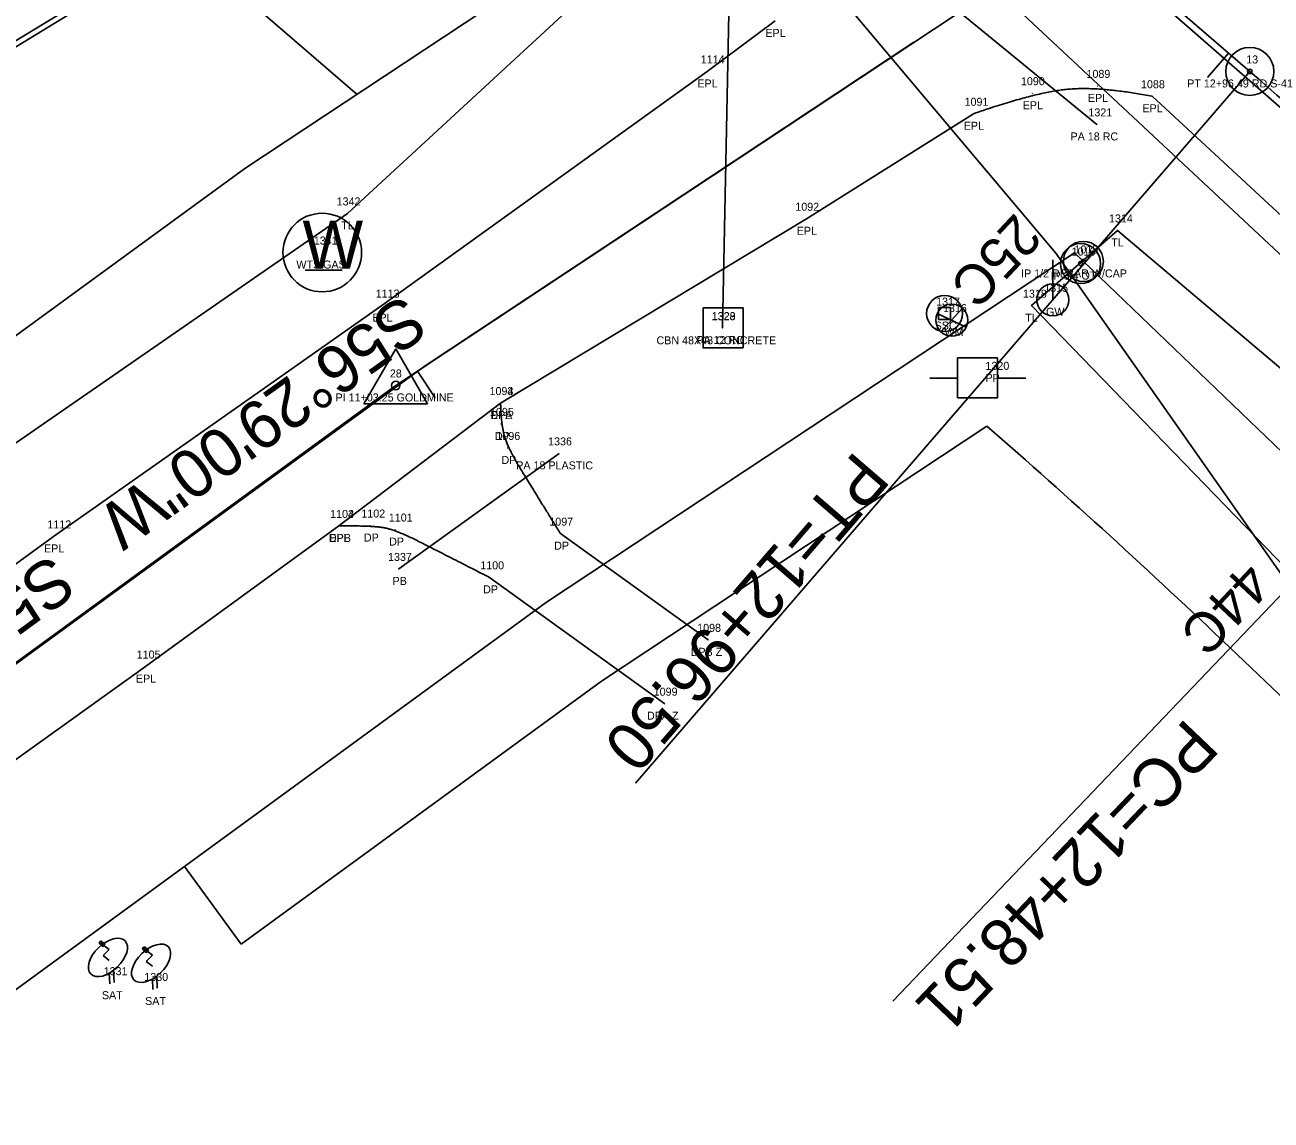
# Model space of a CAD drawing. Extents: x 1812113 to 1819860, y 1177395 to 1181185.
# Drawn here: x 1813697.5 to 1813853.2, y 1178492.8 to 1178629.6 of the extents above; entities that cross this region are included whole.
import ezdxf

# ---------------------------------------------------------------- set-up
doc = ezdxf.new("R2010")
doc.units = 0
for name, color, linetype in [('RD_EX_BldgApp', 7, 'Continuous'), ('RD_EX_BldgApp_txCode', 7, 'Continuous'), ('RD_EX_DR_Inlet', 7, 'Continuous'), ('RD_EX_DR_Inlet_txCode', 7, 'Continuous'), ('RD_EX_DR_Pipe', 7, 'Continuous'), ('RD_EX_DR_Pipe_txCode', 7, 'Continuous'), ('RD_EX_Driveway', 7, 'Continuous'), ('RD_EX_Driveway_txCode', 7, 'Continuous'), ('RD_EX_DV_Prop', 7, 'Continuous'), ('RD_EX_DV_Prop_txCode', 7, 'Continuous'), ('RD_EX_DV_PropPin', 7, 'Continuous'), ('RD_EX_Fence_Other', 7, 'Continuous'), ('RD_EX_Road', 7, 'Continuous'), ('RD_EX_Road_txCode', 7, 'Continuous'), ('RD_EX_RW', 7, 'Continuous'), ('RD_EX_UT', 7, 'Continuous'), ('RD_EX_UT_txCode', 7, 'Continuous'), ('RD_EX_VEG', 7, 'Continuous'), ('RD_EX_VEG_txCode', 7, 'Continuous'), ('RD_HC_CL', 7, 'Continuous'), ('RD_HC_Data', 7, 'Continuous'), ('RD_HC_Data_Tic', 7, 'Continuous'), ('RD_HC_txCode', 7, 'Continuous'), ('RD_PD_ALT3_LnLine', 7, 'Continuous'), ('RD_PD_PatLn1', 7, 'Continuous'), ('RD_PD_RW', 7, 'Continuous'), ('RD_SMD_Locator', 7, 'Continuous')]:
    doc.layers.add(name, color=color, linetype=linetype)

msp = doc.modelspace()

# ---------------------------------------------------------------- linework, layer by layer
at = {"layer": 'RD_EX_BldgApp'}
for p, q in [((1813707.25, 1178514.39), (1813706.86, 1178514.78)), ((1813708.04, 1178514.07), (1813706.93, 1178514.91)), ((1813707.1, 1178515.07), (1813707.53, 1178514.71)), ((1813707.14, 1178514.81), (1813707.14, 1178514.81)), ((1813707.25, 1178514.79), (1813707.25, 1178514.79)), ((1813707.53, 1178514.71), (1813707.25, 1178514.39)), ((1813707.27, 1178513.31), (1813708.04, 1178514.07)), ((1813712.65, 1178513.67), (1813712.26, 1178514.05)), ((1813713.44, 1178513.35), (1813712.33, 1178514.18)), ((1813712.5, 1178514.35), (1813712.93, 1178513.98)), ((1813712.54, 1178514.09), (1813712.54, 1178514.09)), ((1813712.65, 1178514.07), (1813712.65, 1178514.07)), ((1813712.93, 1178513.98), (1813712.65, 1178513.67)), ((1813708.04, 1178512.69), (1813707.27, 1178513.31)), ((1813712.67, 1178512.58), (1813713.44, 1178513.35)), ((1813713.44, 1178511.97), (1813712.67, 1178512.58)), ((1813708.04, 1178511.13), (1813708.11, 1178509.79)), ((1813708.58, 1178511.42), (1813708.65, 1178509.96)), ((1813713.98, 1178510.69), (1813714.05, 1178509.24)), ((1813713.44, 1178510.41), (1813713.51, 1178509.06))]:
    msp.add_line(p, q, dxfattribs=at)
for centre in [(1813707.88, 1178513.08), (1813713.28, 1178512.35)]:
    msp.add_ellipse(centre, major_axis=(-2.15, -2.07), ratio=0.564687, dxfattribs=at)
for centre in [(1813706.99, 1178514.92), (1813712.39, 1178514.2)]:
    msp.add_ellipse(centre, major_axis=(0.099, 0.164), ratio=0.846225, start_param=6.138676, end_param=9.218032, dxfattribs=at)
at = {"layer": 'RD_EX_DR_Inlet'}
msp.add_line((1813787.23, 1178589.25), (1813787.23, 1178594.25), dxfattribs=at)
msp.add_lwpolyline([(1813787.23, 1178589.25), (1813787.23, 1178594.25), (1813782.23, 1178594.25), (1813782.23, 1178589.25)], close=True, dxfattribs=at)
at = {"layer": 'RD_EX_DR_Pipe'}
for p, q in [((1813831.42, 1178617.18), (1813794.72, 1178647.24)), ((1813784.67, 1178591.74), (1813785.57, 1178637.96)), ((1813764.24, 1178576.07), (1813744.22, 1178561.63))]:
    msp.add_line(p, q, dxfattribs=at)
at = {"layer": 'RD_EX_Driveway'}
for p, q in [((1813764.4, 1178566.04), (1813782.88, 1178552.77)), ((1813777.44, 1178544.79), (1813755.53, 1178560.58))]:
    msp.add_line(p, q, dxfattribs=at)
for points in [[(1813756.93, 1178582.36), (1813756.99, 1178579.76), (1813757.82, 1178576.75), (1813761.11, 1178571.4), (1813764.4, 1178566.04)], [(1813736.74, 1178567), (1813740.64, 1178567.05), (1813743.79, 1178566.55), (1813749.66, 1178563.57), (1813755.53, 1178560.58)]]:
    msp.add_open_spline(points, degree=2, dxfattribs=at)
at = {"layer": 'RD_EX_DV_Prop'}
for p, q in [((1813747.53, 1178587.02), (1813808.57, 1178627.44)), ((1814007.16, 1178429.49), (1813828.61, 1178601.13)), ((1813582.74, 1178466.98), (1813747.53, 1178587.02))]:
    msp.add_line(p, q, dxfattribs=at)
at = {"layer": 'RD_EX_DV_PropPin'}
for centre, radius in [((1813829.73, 1178600.06), 2.5), ((1813829.38, 1178599.79), 2.5), ((1813829.38, 1178599.79), 0.25), ((1813829.73, 1178600.06), 0.25)]:
    msp.add_circle(centre, radius, dxfattribs=at)
at = {"layer": 'RD_EX_Fence_Other'}
msp.add_lwpolyline([(1813689.16, 1178653.47), (1813706.15, 1178633.63), (1813541.42, 1178533.61)], dxfattribs=at)
at = {"layer": 'RD_EX_Road'}
for p, q in [((1813782.72, 1178623.8), (1813791.22, 1178630.12)), ((1813742.11, 1178594.54), (1813782.72, 1178623.8)), ((1813875.67, 1178586.1), (1813838.32, 1178620.7)), ((1813815.99, 1178618.51), (1813795.14, 1178605.39)), ((1813795.14, 1178605.39), (1813756.93, 1178582.36)), ((1813701.1, 1178565.69), (1813742.11, 1178594.54)), ((1813756.93, 1178582.36), (1813736.74, 1178567)), ((1813736.74, 1178567), (1813712.58, 1178549.43)), ((1813659.38, 1178535.26), (1813701.1, 1178565.69)), ((1813712.58, 1178549.43), (1813670.71, 1178519.43))]:
    msp.add_line(p, q, dxfattribs=at)
msp.add_open_spline([(1813838.32, 1178620.7), (1813831.51, 1178622), (1813823.35, 1178621.08), (1813815.99, 1178618.51)], degree=2, dxfattribs=at)
at = {"layer": 'RD_EX_RW'}
for p, q in [((1813782.5, 1178649.75), (1813724.98, 1178611.66)), ((1813724.98, 1178611.66), (1813565.45, 1178495.22)), ((1813828.61, 1178601.13), (1813762.68, 1178557.46)), ((1813762.68, 1178557.46), (1813604.36, 1178441.91))]:
    msp.add_line(p, q, dxfattribs=at)
at = {"layer": 'RD_EX_UT'}
for p, q in [((1813825.91, 1178595.26), (1813825.91, 1178600.26)), ((1813732.53, 1178598.96), (1813737.16, 1178598.96)), ((1813811.45, 1178593.56), (1813815.09, 1178591.85)), ((1813813.15, 1178594.29), (1813811.65, 1178594.29)), ((1813811.65, 1178594.29), (1813811.65, 1178592.79)), ((1813811.94, 1178591.27), (1813814.6, 1178594.16)), ((1813813.15, 1178592.79), (1813813.15, 1178594.29)), ((1813811.65, 1178592.79), (1813813.15, 1178592.79)), ((1813818.99, 1178588.01), (1813813.99, 1178588.01)), ((1813813.99, 1178588.01), (1813813.99, 1178583.01)), ((1813818.99, 1178583.01), (1813818.99, 1178588.01)), ((1813810.56, 1178585.45), (1813814.03, 1178585.45)), ((1813818.92, 1178585.45), (1813822.56, 1178585.45)), ((1813813.99, 1178583.01), (1813818.99, 1178583.01))]:
    msp.add_line(p, q, dxfattribs=at)
msp.add_lwpolyline([(1814122.48, 1178351.31), (1814099.73, 1178371.68), (1813807.05, 1178645.14), (1813817.45, 1178777.9), (1813883.81, 1178790.87)], dxfattribs=at)
for centre, radius in [((1813734.66, 1178601.17), 4.91), ((1813825.91, 1178595.26), 2), ((1813812.4, 1178593.54), 2.25), ((1813813.29, 1178592.73), 2)]:
    msp.add_circle(centre, radius, dxfattribs=at)
at = {"layer": 'RD_EX_VEG'}
for points in [[(1813569.58, 1178500.76), (1813635.35, 1178535.15), (1813737.8, 1178606.06), (1813775.9, 1178641.25), (1813752.75, 1178672.45), (1813690.46, 1178652.62), (1813708.11, 1178634.09), (1813540.71, 1178531.72)], [(1813964.65, 1178448.48), (1813984.61, 1178463.55), (1813943.71, 1178503.46), (1813904.65, 1178537.57), (1813863.79, 1178578.71), (1813833.99, 1178603.93), (1813823.24, 1178594.53), (1813964.65, 1178448.48)]]:
    msp.add_lwpolyline(points, dxfattribs=at)
at = {"layer": 'RD_HC_CL'}
for p, q in [((1813850.52, 1178623.8), (1813755.38, 1178705.86)), ((1813829.91, 1178641.57), (1813743.83, 1178584.56)), ((1813743.83, 1178584.56), (1813584.91, 1178468.56))]:
    msp.add_line(p, q, dxfattribs=at)
msp.add_arc((1813226.77, 1177900.71), 954.94, 46.33932, 49.21843, dxfattribs=at)
at = {"layer": 'RD_HC_Data'}
for p, q in [((1813850.52, 1178623.8), (1813773.78, 1178534.84)), ((1813886.05, 1178591.55), (1813805.93, 1178507.6)), ((1813739.86, 1178582.27), (1813743.83, 1178589.15)), ((1813743.83, 1178589.15), (1813747.8, 1178582.27)), ((1813739.86, 1178582.27), (1813747.8, 1178582.27))]:
    msp.add_line(p, q, dxfattribs=at)
for centre, radius in [((1813850.52, 1178623.8), 3), ((1813850.52, 1178623.8), 0.282), ((1813743.83, 1178584.56), 0.529)]:
    msp.add_circle(centre, radius, dxfattribs=at)
at = {"layer": 'RD_HC_Data_Tic'}
for p, q in [((1813847.86, 1178626.09), (1813845.25, 1178623.06)), ((1813746.54, 1178586.35), (1813748.75, 1178583.02))]:
    msp.add_line(p, q, dxfattribs=at)
at = {"layer": 'RD_PD_ALT3_LnLine'}
for p, q in [((1813826.31, 1178601.1), (1813793.67, 1178639.81)), ((1813854.64, 1178560.7), (1813826.31, 1178601.1))]:
    msp.add_line(p, q, dxfattribs=at)
at = {"layer": 'RD_PD_PatLn1'}
msp.add_line((1813775.64, 1178688.14), (1813886.05, 1178591.55), dxfattribs=at)
at = {"layer": 'RD_PD_RW'}
for p, q in [((1813739, 1178620.94), (1813706.39, 1178649.07)), ((1813817.66, 1178579.49), (1813769.53, 1178547.61)), ((1813883.18, 1178518.26), (1813848.08, 1178551.76)), ((1813769.53, 1178547.61), (1813724.52, 1178514.75)), ((1813724.52, 1178514.75), (1813717.44, 1178524.45))]:
    msp.add_line(p, q, dxfattribs=at)
msp.add_arc((1813226.77, 1177900.71), 899.94, 46.33932, 48.95957, dxfattribs=at)
at = {"layer": 'RD_SMD_Locator'}
for centre in [(1813782.72, 1178623.8), (1813850.52, 1178623.8), (1813823.35, 1178621.08), (1813831.51, 1178622), (1813838.32, 1178620.7), (1813815.99, 1178618.51), (1813831.42, 1178617.18), (1813737.8, 1178606.06), (1813795.14, 1178605.39), (1813833.99, 1178603.93), (1813742.11, 1178594.54), (1813823.24, 1178594.53), (1813784.67, 1178591.74), (1813743.83, 1178584.56), (1813756.93, 1178582.36), (1813756.93, 1178582.36), (1813756.99, 1178579.76), (1813757.82, 1178576.75), (1813764.24, 1178576.07), (1813736.74, 1178567), (1813736.74, 1178567), (1813740.64, 1178567.05), (1813743.79, 1178566.55), (1813701.1, 1178565.69), (1813764.4, 1178566.04), (1813744.22, 1178561.63), (1813755.53, 1178560.58), (1813782.88, 1178552.77), (1813712.58, 1178549.43), (1813777.44, 1178544.79)]:
    msp.add_circle(centre, 0.001, dxfattribs=at)

# ---------------------------------------------------------------- texts
at = {"layer": 'RD_EX_BldgApp_txCode'}
for s, p in [('1331', (1813707.35, 1178510.86)), ('1330', (1813712.43, 1178510.14)), ('SAT', (1813707.13, 1178507.86)), ('SAT', (1813712.53, 1178507.14))]:
    msp.add_text(s, height=1, dxfattribs=at).set_placement(p)
at = {"layer": 'RD_EX_DR_Inlet_txCode'}
for s, p in [('1328', (1813783.3, 1178592.7)), ('CBN 48X48 CONCRETE', (1813776.41, 1178589.7))]:
    msp.add_text(s, height=1, dxfattribs=at).set_placement(p)
at = {"layer": 'RD_EX_DR_Pipe_txCode'}
for s, p in [('1321', (1813830.36, 1178618.18)), ('PA 18 RC', (1813828.13, 1178615.18)), ('1329', (1813783.32, 1178592.74)), ('PA 12 RC', (1813781.38, 1178589.74)), ('1336', (1813762.87, 1178577.07)), ('PA 18 PLASTIC', (1813758.89, 1178574.07)), ('1337', (1813742.87, 1178562.63)), ('PB', (1813743.44, 1178559.63))]:
    msp.add_text(s, height=1, dxfattribs=at).set_placement(p)
at = {"layer": 'RD_EX_Driveway_txCode'}
for s, p in [('1094', (1813755.55, 1178583.36)), ('1095', (1813755.61, 1178580.76)), ('DPA', (1813755.66, 1178580.36)), ('DP', (1813756.21, 1178577.76)), ('1096', (1813756.41, 1178577.75)), ('DP', (1813757.04, 1178574.75)), ('1103', (1813735.64, 1178568)), ('1102', (1813739.54, 1178568.05)), ('1101', (1813742.97, 1178567.55)), ('1097', (1813763.02, 1178567.04)), ('DPB', (1813735.49, 1178565)), ('DP', (1813739.86, 1178565.05)), ('DP', (1813743.01, 1178564.55)), ('DP', (1813763.63, 1178564.04)), ('1100', (1813754.39, 1178561.58)), ('DP', (1813754.75, 1178558.58)), ('1098', (1813781.49, 1178553.77)), ('DPB Z', (1813780.68, 1178550.77)), ('1099', (1813776.06, 1178545.79)), ('DPA Z', (1813775.22, 1178542.79))]:
    msp.add_text(s, height=1, dxfattribs=at).set_placement(p)
at = {"layer": 'RD_EX_DV_Prop_txCode'}
for s, p in [('1016', (1813828.26, 1178600.79)), ('1015', (1813828.62, 1178601.06)), ('IP 1/2 REBAR W/CAP', (1813821.95, 1178598.06)), ('IP 3/4 OT', (1813825.63, 1178597.79))]:
    msp.add_text(s, height=1, dxfattribs=at).set_placement(p)
at = {"layer": 'RD_EX_Road_txCode'}
for s, p in [('EPL', (1813790.01, 1178628.12)), ('1114', (1813781.94, 1178624.8)), ('EPL', (1813781.51, 1178621.8)), ('1090', (1813821.93, 1178622.08)), ('1089', (1813830.12, 1178623)), ('1088', (1813836.93, 1178621.7)), ('EPL', (1813830.3, 1178620)), ('1091', (1813814.89, 1178619.51)), ('EPL', (1813822.15, 1178619.08)), ('EPL', (1813837.11, 1178618.7)), ('EPL', (1813814.79, 1178616.51)), ('1092', (1813793.75, 1178606.39)), ('EPL', (1813793.93, 1178603.39)), ('1113', (1813741.33, 1178595.54)), ('EPL', (1813740.91, 1178592.54)), ('1093', (1813755.55, 1178583.36)), ('EPL', (1813755.73, 1178580.36)), ('1104', (1813735.64, 1178568)), ('1112', (1813700.32, 1178566.69)), ('EPL', (1813735.54, 1178565)), ('EPL', (1813699.9, 1178563.69)), ('1105', (1813711.48, 1178550.43)), ('EPL', (1813711.38, 1178547.43))]:
    msp.add_text(s, height=1, dxfattribs=at).set_placement(p)
at = {"layer": 'RD_EX_UT'}
msp.add_text('W', height=6, dxfattribs=at).set_placement((1813732.19, 1178599.16))
at = {"layer": 'RD_EX_UT_txCode'}
for s, p in [('1341', (1813733.6, 1178602.17)), ('WTS GAS', (1813731.42, 1178599.17)), ('1315', (1813824.84, 1178596.26)), ('1317', (1813811.34, 1178594.54)), ('1316', (1813812.2, 1178593.73)), ('GW', (1813825.06, 1178593.26)), ('SSC', (1813811.15, 1178591.54)), ('WM', (1813812.38, 1178590.73)), ('1320', (1813817.5, 1178586.51)), ('PP', (1813817.5, 1178585.01))]:
    msp.add_text(s, height=1, dxfattribs=at).set_placement(p)
at = {"layer": 'RD_EX_VEG_txCode'}
for s, p in [('1342', (1813736.45, 1178607.06)), ('1314', (1813832.93, 1178604.93)), ('TL', (1813737.03, 1178604.06)), ('TL', (1813833.22, 1178601.93)), ('1318', (1813822.18, 1178595.53)), ('TL', (1813822.47, 1178592.53))]:
    msp.add_text(s, height=1, dxfattribs=at).set_placement(p)
at = {"layer": 'RD_HC_Data'}
for s, rotation, p in [('S56%%d29\'00"W', 215.4947, (1813744.8, 1178596.14)), ('PT=12+96.50', 229.2184, (1813801.27, 1178576.56)), ('S53%%d52\'28"W', 216.1257, (1813700.81, 1178563.66)), ('PC=12+48.51', 226.3393, (1813842.62, 1178543.15))]:
    msp.add_text(s, height=6, rotation=rotation, dxfattribs=at).set_placement(p)
at = {"layer": 'RD_HC_txCode'}
for s, p in [('13', (1813850.07, 1178624.8)), ('PT 12+96.49 RD S-41', (1813842.7, 1178621.8)), ('28', (1813743.1, 1178585.56)), ('PI 11+03.25 GOLDMINE', (1813736.32, 1178582.56))]:
    msp.add_text(s, height=1, dxfattribs=at).set_placement(p)
at = {"layer": 'RD_PD_ALT3_LnLine'}
for s, p in [('25C', (1813821.24, 1178606.27)), ('44C', (1813849.96, 1178562.8))]:
    msp.add_text(s, height=5, rotation=226.7234, dxfattribs=at).set_placement(p)

doc.saveas('drawing.dxf')
